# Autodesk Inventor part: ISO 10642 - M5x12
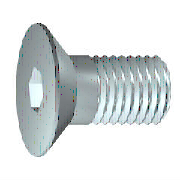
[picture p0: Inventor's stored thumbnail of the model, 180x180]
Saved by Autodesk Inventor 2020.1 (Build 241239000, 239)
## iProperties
Created: 2019-01
Part Number: ISO 10642 - M5x12
Material: Stahl, weich
Description: Senkschrauben mit Innensechskant
Document SubType Name: Modeling
Standard: ISO 10642
Designer: lutzd
Standards Organization: ISO
Language: de-DE
Size Designation: M5x12
Categories: <MemberInstance><Categories><Category DisplayName="Verbindungselemente" InternalName="e4da775c-781d-43d5-af7c-5136215cf5a6" Mnemonic="FSTN"><Category DisplayNam
Mass: 2.35216 g
Surface Area: 3.553 cm^2
Volume: 0.299638 cm^3
Density: 7.85 g/cm^3
Appearance: Halbpoliert
IsCustomPart: 0
Author: lutzd
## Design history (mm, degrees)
node "WorkPoint1"
sketch "Skizze2"
  geometry: L1 (-2.5, -12)-(0, -12); L2 (-2.5, -2.8)-(-2.5, -12); L3 (-5, -0.3)-(-2.5, -2.8); L4 (-5, 0)-(-5, -0.3); L5 (0, 0)-(-5, 0); L6 (0, -12)-(0, 0); L7 (0, -12)-(0, 0); L8 (0, -14.4)-(0, 2.4) reference; L9 (1, 0)-(-6, 0) reference
  constraints: 14 end point, 3 vertical, 2 horizontal
  dimensions: "d3" = 5 distance of L5.start L4.start (= 0.5 x dk); "d5" = 2.5 distance of L1.start L1.end (= 0.5 x NND); "d7" = 12 distance of L1.end L5.start (= NLG); "ParC" = 0.3 distance of L4.start L3.start; "d22" = 0 distance between parallel lines of L8 L6; "d23" = 0 distance between parallel lines of L9 L5; "d43" = 45 deg angle of L6 L3 (= 0.5 x ang)
revolve "Drehung1" stored, may be unused: angle "d8" = 360 deg
node "MSC_A1"
node "MSC_PF1"
node "MSC_PT1"
body "Solid1"
node "Skizze1"
sketch "Skizze3"
  geometry: L1 (-1.5, 0.866)-(-1.5, -0.866); L2 (0, 1.732)-(-1.5, 0.866); L3 (1.5, 0.866)-(0, 1.732); L4 (1.5, -0.866)-(1.5, 0.866); L5 (0, -1.732)-(1.5, -0.866); L6 (-1.5, -0.866)-(0, -1.732); C1 r 1.5 at (0, 0); C2 r 2.5 at (0, 0) reference
  constraints: 12 end point, 6 tangent, 2 parallel, 2 vertical, 1 centre point, 1 concentric
  dimensions: "d11" = 3 diameter of C1 (= ParS); "d13" = 120 deg angle of L1 L2; "d15" = 120 deg angle of L6 L1
extrude "Extrusion1" cut sketch "Skizze3" distance "d16" = 2.3 (= ParT); taper "d17" = 0 deg
fillet "Rundung1" dims "d18" = 0.2 (= r)
chamfer "Fase1" distance "d19" = 0.4 (= 0.5 x PTC); stored, may be unused: angle "d20" = 45 deg, second distance "d39" = 0.4 (= 0.5 x PTC)
feature "Gewinde1" dims "d35" = 0, "b" = 7.6
other parameters: "NND" = 5 [user parameter; used in 2 equation terms], "PTC" = 0.8 [user parameter; used in 2 equation terms], "ParK" = 2.8 [user parameter], "ParS" = 3 [user parameter; used in 1 equation term], "ParT" = 2.3 [user parameter; used in 1 equation term], "r" = 0.2 [user parameter; used in 1 equation term], "NLG" = 12 [user parameter; used in 1 equation term], "d0" = 45 deg (derived), "d2" = 3 (derived), "d4" = 1.5 (derived), "d6" = 8 (derived), "d9" = 0, "d10" = 2 (derived), "d12" = 120 deg (derived), "d14" = 120 deg (derived), "d37" = 0, "d38" = 0, "d40" = 0, "d41" = 0, "d42" = 0, "ang" = 90 deg [user parameter; used in 1 equation term], "THREADDIA" = 5 (= NND) [user parameter]
